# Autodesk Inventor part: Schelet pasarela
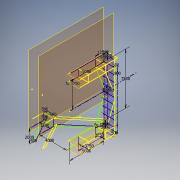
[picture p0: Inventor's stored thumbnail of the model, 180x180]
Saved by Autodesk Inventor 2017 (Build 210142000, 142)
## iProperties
Created: 2017-11
Part Number: Schelet pasarela
Material: Generic
Document SubType Name: Modeling
Designer: iusti
Density: 1 g/cm^3
Appearance: Default
Author: iusti
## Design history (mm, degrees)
sketch "Sketch1"
  geometry: L1 (0, 3750)-(5000, 3750); L2 (5000, -3750)-(0, -3750); L3 (0, 4750)-(5000, 4750); L4 (0, -4750)-(5000, -4750); L5 (5000, 4750)-(5000, -4750); 1 further point
  constraints: 10 end point, 3 horizontal, 1 vertical
  dimensions: "d0" = 5000 distance of L1.start L1.end; "d1" = 7500 distance of L1.end L2.start; "d2" = 5000 distance of L2.start L2.end; "d3" = 3750 distance from line of point (0, 0) L1 (= 0.5 x d1); "d4" = 1000 distance of L2.start L4.end; "d7" = 1000 distance between parallel lines of L1 L3
workplane "Work Plane1"
sketch "Sketch2"
  geometry: L1 (0, 4750)-(5000, 4750) reference; L2 (0, 3750)-(5000, 3750) reference; L3 (5000, -3750)-(0, -3750) reference; L4 (0, -4750)-(5000, -4750) reference; L5 (5000, 4750)-(5000, -4750) reference; 1 further point
workplane "Work Plane2"
workplane "Work Plane3"
sketch "Sketch3"
  geometry: L1 (0, 5000)-(1500, 5000); 1 further point
  constraints: 2 end point, 1 horizontal
sketch "Sketch4"
  geometry: L1 (0, 5000)-(1500, 5000) reference; 1 further point
workplane "Work Plane4"
sketch "Sketch5" dims "d16" = 10
  geometry: L1 (0, -4750)-(-1500, -4750) reference; L2 (0, 4750)-(-1500, 4750); L3 (0, 4750)-(-1500, 4750) reference; L4 (0, 4750)-(0, -4750); L5 (0, 3800)-(-1500, 3800); L6 (0, 2850)-(-1500, 2850); L7 (0, 1900)-(-1500, 1900); L8 (0, 950)-(-1500, 950); L9 (0, 0)-(-1500, 0); L10 (0, -950)-(-1500, -950); L11 (0, -1900)-(-1500, -1900); L12 (0, -2850)-(-1500, -2850); L13 (0, -3800)-(-1500, -3800); 19 further points
  constraints: 22 end point, 1 horizontal, 1 perpendicular, 1 vertical, 45 other
  dimensions: "d13" = 950 distance of L2.start L5.start
sketch "Sketch7"
  geometry: L1 (3750, -3754.14)-(5000, -500); L2 (3750, 3722.685)-(5000, 500); L3 (5000, 4750)-(5000, -4750) reference; 1 further point
  constraints: 4 end point, 2 point on line
  dimensions: "d20" = 1250 distance from line of L3 L1.start (= d21); "d21" = 1250 distance from line of L3 L2.start; "d22" = 1000 distance of L2.end L1.end; "d23" = 500 vertical distance of L1.end point (0, 0) (= 0.5 x d22)
sketch "Sketch8"
  geometry: L1 (3750, 3722.685)-(5000, 500) reference; L2 (3750, -3754.14)-(5000, -500) reference; 1 further point
sketch "Sketch10"
  geometry: L1 (5000, -3750)-(0, -3750) reference; L2 (0, -4750)-(5000, -4750) reference; L3 (0, 3750)-(5000, 3750) reference; L4 (0, 4750)-(5000, 4750) reference; L5 (3750, -4750)-(3750, -3750); L6 (1250, -3750)-(1250, -4750); L7 (5000, 4750)-(5000, -4750) reference; L8 (0, 0)-(9911.032, 0); L9 (3750, 4750)-(3750, 3750); L10 (1250, 3750)-(1250, 4750)
  constraints: 10 end point, 4 point on line, 4 symmetric about line, 2 perpendicular, 1 horizontal
  dimensions: "d24" = 1250 distance between parallel lines of L5 L7; "d25" = 3750 distance between parallel lines of L6 L7 (computed from d2)
sketch "Sketch11"
  geometry: L1 (3750, 4750)-(3750, 3750) reference; L2 (1250, 3750)-(1250, 4750) reference; L3 (1250, -3750)-(1250, -4750) reference; L4 (3750, -4750)-(3750, -3750) reference; 1 further point
sketch "Sketch12"
  geometry: L1 (1500, 3750)-(0, 3750); L2 (1500, 1250)-(0, 1250); 1 further point
  constraints: 4 end point, 2 horizontal
sketch "Sketch13"
  geometry: L1 (1500, 3750)-(0, 3750) reference; L2 (1500, 1250)-(0, 1250) reference; 1 further point
sketch "Sketch14"
  geometry: L1 (-4000, 0)-(-4000, 1614.608); L2 (-4000, 1614.608)-(-5500, 1614.608); L3 (-5500, 1614.608)-(-5500, 0); L4 (0, 5000)-(-4000, 1614.608); 1 further point
  constraints: 8 end point, 1 horizontal, 1 perpendicular, 1 vertical
  dimensions: "d27" = 4000 distance from line of L1 point (0, 0); "d28" = 1500 distance of L1.end L2.end
workplane "Work Plane6"
sketch "Sketch15"
  geometry: L1 (0, 5000)-(-4000, 1614.608) reference; L2 (-4000, 0)-(-4000, 1614.608) reference; L3 (-4000, 1614.608)-(-5500, 1614.608) reference; L4 (-5500, 1614.608)-(-5500, 0) reference; 1 further point
workplane "Work Plane7"
sketch "Sketch16"
  geometry: L1 (1614.608, -4750)-(1614.608, -3750); 1 further point
  constraints: 2 end point, 1 vertical
workplane "Work Plane8"
sketch "Sketch17"
  geometry: L1 (1614.608, -4750)-(1614.608, -3714.096); 2 further points
  constraints: 2 end point, 1 vertical
sketch "Sketch18"
  geometry: L1 (1500, 1250)-(0, 1250) reference; L2 (1500, 3750)-(0, 3750) reference; 1 further point
workplane "Work Plane9"
sketch "Sketch19"
  geometry: L1 (1500, 1250)-(0, 1250) reference; L2 (1500, 3750)-(0, 3750) reference; 1 further point
sketch "Sketch20"
  geometry: L1 (1614.608, -4750)-(0, -6750); 2 further points
  constraints: 2 end point
  dimensions: "d33" = 2000 distance of point (0, -4750) L1.end
sketch "Sketch21"
  geometry: L1 (1614.608, -4750)-(0, -6750) reference; 1 further point
sketch "Sketch22"
  geometry: L1 (0, -6750)-(500, -6750); L2 (1614.608, -4750)-(2114.608, -4750); L3 (1614.608, -3750)-(2114.608, -3750); L4 (2114.608, -3750)-(2114.608, -4750); L5 (500, -6750)-(2114.608, -4750); 1 further point
  constraints: 10 end point, 3 horizontal
  dimensions: "d34" = 500 distance of L1.start L1.end; "d35" = 500 distance of L2.start L2.end; "d36" = 500 distance of L3.start L3.end
sketch "Sketch23"
  geometry: L1 (500, -6750)-(2114.608, -4750) reference; L2 (0, -6750)-(500, -6750) reference; L3 (1614.608, -4750)-(2114.608, -4750) reference; 1 further point
sketch "Sketch24"
  geometry: L1 (1500, 5000)-(1500, 5500); L2 (0, 5000)-(0, 5500); L3 (0, 5500)-(1500, 5500); L4 (0, 5500)-(-4000, 2114.608); 1 further point
  constraints: 8 end point, 2 vertical
  dimensions: "d37" = 500 distance of L1.start L1.end; "d38" = 500 distance of L2.start L2.end
sketch "Sketch25" dims "d53" = 10
  geometry: L1 (5000, 3750.525)-(5500, 3750.525); L2 (5500, 3750.525)-(5500, -4750); L3 (5500, 3175.591)-(5007.123, 3175.591); L4 (5000, -3750)-(5500, -3750); L5 (5500, 2375.591)-(5007.123, 2375.591); L6 (5500, 1575.591)-(5007.123, 1575.591); L7 (5500, 775.591)-(5007.123, 775.591); L8 (5500, -24.409)-(5007.123, -24.409); L9 (5500, -824.409)-(5007.123, -824.409); L10 (5500, -1624.409)-(5007.123, -1624.409); L11 (5500, -2424.409)-(5007.123, -2424.409); L12 (5500, -3224.409)-(5007.123, -3224.409); L13 (5500, -4253.829)-(5000, -4253.829); 2 further points
  constraints: 26 end point, 4 horizontal, 3 point on line, 1 perpendicular, 1 vertical, 24 other
  dimensions: "d39" = 500 distance of L1.start L1.end; "d50" = 800 distance of L3.start L5.start
sketch "Sketch26"
  geometry: L1 (5000, 3750.525)-(5500, 3750.525) reference; L2 (5500, -4253.829)-(5000, -4253.829) reference; L3 (5000, 4750)-(5500, 4750); L4 (5500, 4750)-(5500, -4253.829); L5 (5015.051, 4290.822)-(5500, 4290.822); L6 (5500, 3175.591)-(5007.123, 3175.591) reference; L7 (5500, 2375.591)-(5007.123, 2375.591) reference; L8 (5500, 1575.591)-(5007.123, 1575.591) reference; L9 (5500, 775.591)-(5007.123, 775.591) reference; L10 (5500, -24.409)-(5007.123, -24.409) reference; L11 (5500, -824.409)-(5007.123, -824.409) reference; L12 (5500, -1624.409)-(5007.123, -1624.409) reference; L13 (5500, -2424.409)-(5007.123, -2424.409) reference; L14 (5500, -3224.409)-(5007.123, -3224.409) reference; L15 (5000, -3750)-(5500, -3750) reference; 1 further point
  constraints: 6 end point, 1 horizontal, 1 perpendicular, 1 point on line
  dimensions: "d55" = 500 distance of L3.start L3.end
sketch "Sketch27"
  geometry: L1 (0, 5500)-(1500, 5500) reference; L2 (1500, 5000)-(1500, 5500) reference; 1 further point
sketch "Sketch28" dims "d61" = 10
  geometry: L1 (0, 5000)-(0, 0) reference; L2 (0, 5500)-(-4000, 2114.608) reference; L3 (-4000, 1614.608)-(-4000, 2114.608) reference; L4 (-4000, 2114.608)-(-5500, 2114.608); L5 (-4345.604, 2114.608)-(-4345.604, 1614.608); L6 (-4745.604, 2114.608)-(-4745.604, 1614.608); L7 (-5145.604, 2114.608)-(-5145.604, 1614.608); 1 further point
  constraints: 8 end point, 2 horizontal, 1 point on line, 1 vertical, 6 other
  dimensions: "d58" = 400 distance of L5.start L6.start
